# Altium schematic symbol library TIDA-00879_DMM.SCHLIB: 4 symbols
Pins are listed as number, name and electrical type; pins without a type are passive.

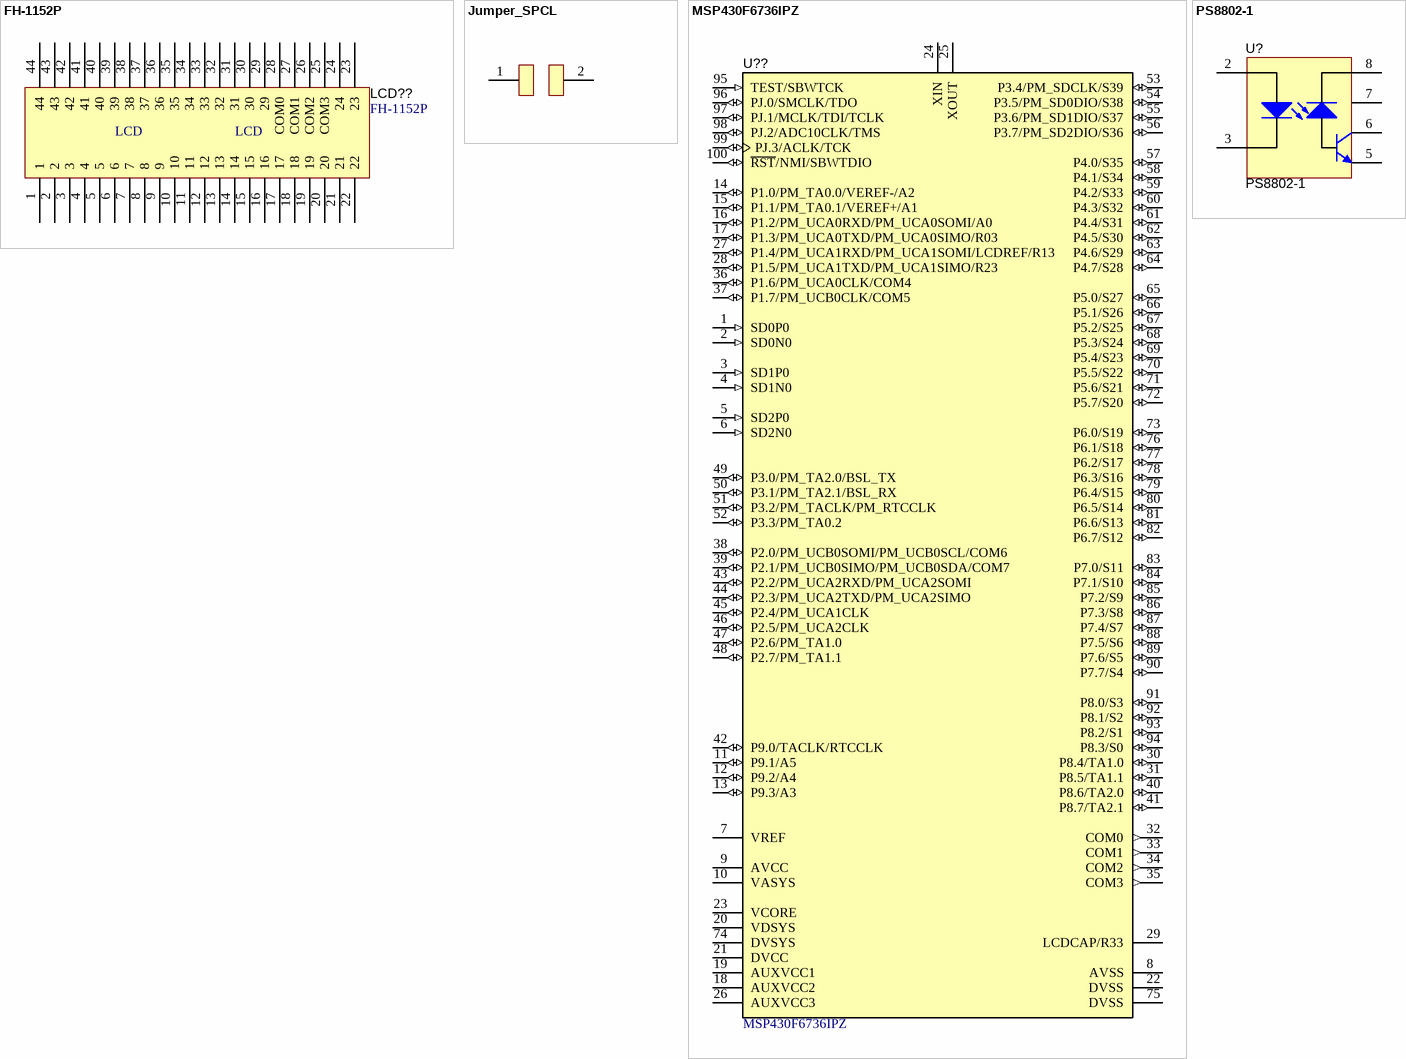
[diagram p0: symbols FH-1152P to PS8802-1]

## FH-1152P
designator LCD??
footprint FH-1152P
pins: 1, 2, 3, 4, 5, 6, 7, 8, 9, 10, 11, 12, 13, 14, 15, 16, 17, 18, 19, 20, 21, 22, 23, 24, 25 COM3, 26 COM2, 27 COM1, 28 COM0, 29, 30, 31, 32, 33, 34, 35, 36, 37, 38, 39, 40, 41, 42, 43, 44

## Jumper_SPCL
designator J?, comment Used in BOM report  (value not drawn)
SymbolVersion: use current date i.e. 2008-05-20; SymbolCreator: Use a-id; CompType: Used in some BOM reports.  Useful for finding later.; U/M: EA, IN, or GM
footprint JUMPER_SPCL
pins: 1, 2

## MSP430F6736IPZ
designator U??
25 MHz Mixed Signal Microcontroller with 128 KB Flash, 8192 B SRAM and 72 GPIOs, -40 to 85 degC, 100-pin QFP (PZ), Green (RoHS & no Sb/Br); Alternate Manufacturer: Texas Instruments; Alternate PartNumber: Equivalent; ADC: 10-bit SAR; ADC Channels: 8; Brown Out Reset: Yes; DMA: 3; Flash(KB): 128; Frequency(MHz): 25; GPIO: 72; LCD Segments: 320; Multiplier: 32x32; Pin/Package: 100LQFP, 80LQFP; Real-Time Clock: Yes, with battery backup; SRAM(B): 8192; SubFamily: 6 Series with LCD; Timers - 16-bit: 4; USCI_B (I2C & SPI): 1
footprint PZ0100A_N (QFP, 100-Leads, Body 14x14mm, Pitch 0.5mm, IPC Medium Density)
footprint PZ0100A_L (QFP, 100-Leads, Body 14x14mm, Pitch 0.5mm, IPC High Density)
footprint PZ0100A_M (QFP, 100-Leads, Body 14x14mm, Pitch 0.5mm, IPC Low Density)
pins: 1 SD0P0 (in) "SD24_B positive analog input for converter 0", 2 SD0N0 (in) "SD24_B negative analog input for converter 0", 3 SD1P0 (in) "SD24_B positive analog input for converter 1", 4 SD1N0 (in) "SD24_B negative analog input for converter 1", 5 SD2P0 (in) "SD24_B positive analog input for converter 2", 6 SD2N0 (in) "SD24_B negative analog input for converter 2", 7 VREF "SD24_B external reference voltage", 8 AVSS (power) "Analog ground supply", 9 AVCC (power) "Analog power supply", 10 VASYS (power) "Analog power supply selected between AVCC, AUXVCC1, AUXVCC2. Connect recommended capacitor value of CVSYS", 11 P9.1/A5 (io), 12 P9.2/A4 (io), 13 P9.3/A3 (io), 14 P1.0/PM_TA0.0/VEREF-/A2 (io), 15 P1.1/PM_TA0.1/VEREF+/A1 (io), 16 P1.2/PM_UCA0RXD/PM_UCA0SOMI/A0 (io), 17 P1.3/PM_UCA0TXD/PM_UCA0SIMO/R03 (io), 18 AUXVCC2 (power) "Auxiliary power supply AUXVCC2", 19 AUXVCC1 (power) "Auxiliary power supply AUXVCC2", 20 VDSYS (power) "Digital power supply selected between DVCC, AUXVCC1, AUXVCC2. Connect recommended capacitor value of CVSYS", 21 DVCC (power) "Digital power supply", 22 DVSS (power) "Digital ground supply", 23 VCORE "Regulated core power supply (internal use only, no external current loading)", 24 XIN "Input terminal for crystal oscillator", 25 XOUT "Output terminal for crystal oscillator", 26 AUXVCC3 (power) "Auxiliary power supply AUXVCC3 for back up subsystem", 27 P1.4/PM_UCA1RXD/PM_UCA1SOMI/LCDREF/R13 (io), 28 P1.5/PM_UCA1TXD/PM_UCA1SIMO/R23 (io), 29 LCDCAP/R33, 30 P8.4/TA1.0 (io), 31 P8.5/TA1.1 (io), 32 COM0 (out) "LCD common output COM0 for LCD backplane", 33 COM1 (out) "LCD common output COM1 for LCD backplane", 34 COM2 (out) "LCD common output COM2 for LCD backplane", 35 COM3 (out) "LCD common output COM3 for LCD backplane", 36 P1.6/PM_UCA0CLK/COM4 (io), 37 P1.7/PM_UCB0CLK/COM5 (io), 38 P2.0/PM_UCB0SOMI/PM_UCB0SCL/COM6 (io), 39 P2.1/PM_UCB0SIMO/PM_UCB0SDA/COM7 (io), 40 P8.6/TA2.0 (io), 41 P8.7/TA2.1 (io), 42 P9.0/TACLK/RTCCLK (io), 43 P2.2/PM_UCA2RXD/PM_UCA2SOMI (io), 44 P2.3/PM_UCA2TXD/PM_UCA2SIMO (io), 45 P2.4/PM_UCA1CLK (io), 46 P2.5/PM_UCA2CLK (io), 47 P2.6/PM_TA1.0 (io), 48 P2.7/PM_TA1.1 (io), 49 P3.0/PM_TA2.0/BSL_TX (io), 50 P3.1/PM_TA2.1/BSL_RX (io), 51 P3.2/PM_TACLK/PM_RTCCLK (io), 52 P3.3/PM_TA0.2 (io), 53 P3.4/PM_SDCLK/S39 (io), 54 P3.5/PM_SD0DIO/S38 (io), 55 P3.6/PM_SD1DIO/S37 (io), 56 P3.7/PM_SD2DIO/S36 (io), 57 P4.0/S35 (io), 58 P4.1/S34 (io), 59 P4.2/S33 (io), 60 P4.3/S32 (io), 61 P4.4/S31 (io), 62 P4.5/S30 (io), 63 P4.6/S29 (io), 64 P4.7/S28 (io), 65 P5.0/S27 (io), 66 P5.1/S26 (io), 67 P5.2/S25 (io), 68 P5.3/S24 (io), 69 P5.4/S23 (io), 70 P5.5/S22 (io), 71 P5.6/S21 (io), 72 P5.7/S20 (io), 73 P6.0/S19 (io), 74 DVSYS (power) "Digital power supply for I/Os", 75 DVSS (power) "Digital ground supply", 76 P6.1/S18 (io), 77 P6.2/S17 (io), 78 P6.3/S16 (io), 79 P6.4/S15 (io), 80 P6.5/S14 (io), 81 P6.6/S13 (io), 82 P6.7/S12 (io), 83 P7.0/S11 (io), 84 P7.1/S10 (io), 85 P7.2/S9 (io), 86 P7.3/S8 (io), 87 P7.4/S7 (io), 88 P7.5/S6 (io), 89 P7.6/S5 (io), 90 P7.7/S4 (io), 91 P8.0/S3 (io), 92 P8.1/S2 (io), 93 P8.2/S1 (io), 94 P8.3/S0 (io), 95 TEST/SBWTCK (in), 96 PJ.0/SMCLK/TDO (io), 97 PJ.1/MCLK/TDI/TCLK (io), 98 PJ.2/ADC10CLK/TMS (io), 99 PJ.3/ACLK/TCK (io), 100 ~{RST}/NMI/SBWTDIO (io)

## PS8802-1
designator U?
Manufacturer: Used in BOM report; SymbolVersion: use current date i.e. 2008-05-20; SymbolCreator: Use LDAP id; CompType: Used in some BOM reports.  Useful for finding later.; U/M: EA, IN, or GM
footprint SO-8 (SOIC, 8-Leads, Body 5.0x4.0mm (max), Pitch 1.27mm, IPC Medium Density)
pins: 1 hidden, 2, 3, 4 hidden, 5, 6, 7, 8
